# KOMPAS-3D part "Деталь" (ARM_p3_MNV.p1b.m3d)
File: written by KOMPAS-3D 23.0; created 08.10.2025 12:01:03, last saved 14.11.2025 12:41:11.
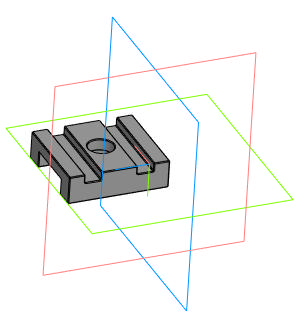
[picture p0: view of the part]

Document properties: Автор: ADMIN; Полное имя файла: D:\YandexDisk\Model\NVG\ARM mkII\ARM p3 MNV.p1b.m3d

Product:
- Part/product: Деталь
    Масса: 0.016505

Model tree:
1. Эскиз:1
2. Элемент выдавливания:1
     Расстояние 1 = 25
3. Эскиз:2  (with: Элемент выдавливания:1)
4. Элемент выдавливания:2
5. Эскиз:3  (with: Элемент выдавливания:1)
6. Элемент выдавливания:3
     Расстояние 2 = 22
7. Фаска:1  (with: Элемент выдавливания:2, Элемент выдавливания:3, Элемент выдавливания:1)
     Угол = 45; Длина 1 = 0.2; Длина 2 = 0.2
